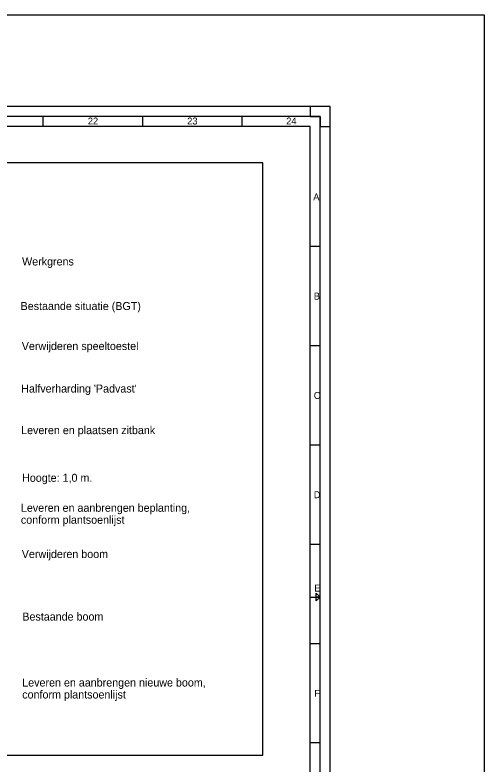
# Model space of a CAD drawing. Extents: x 192664 to 192925, y 446334 to 446521.
# Drawn here: x 192877.8 to 192925, y 446445.5 to 446521 of the extents above; entities that cross this region are included whole.
import ezdxf

# ---------------------------------------------------------------- set-up
doc = ezdxf.new("R2010")
doc.units = 0
for name, color, linetype in [('201011 legenda', 7, 'Continuous'), ('201020 hulplijnen', 7, 'Continuous'), ('X-XX-AL-TEKENBLAD-S', 7, 'Continuous'), ('X-XX-AL-TEKENBLAD_KADER-G', 7, 'Continuous')]:
    doc.layers.add(name, color=color, linetype=linetype)

msp = doc.modelspace()

# ---------------------------------------------------------------- linework, layer by layer
at = {"layer": '201020 hulplijnen'}
msp.add_lwpolyline([(192864.958, 446446.417), (192902.755, 446446.417), (192902.755, 446506.094), (192864.958, 446506.094)], close=True, dxfattribs=at)
at = {"layer": 'X-XX-AL-TEKENBLAD-S'}
for p, q in [((192909.543, 446511.756), (192671.743, 446511.756)), ((192909.543, 446343.556), (192909.543, 446511.756)), ((192908.543, 446510.756), (192674.743, 446510.756)), ((192880.643, 446510.756), (192880.643, 446509.756)), ((192890.643, 446510.756), (192890.643, 446509.756)), ((192900.643, 446510.756), (192900.643, 446509.756)), ((192908.543, 446344.556), (192908.543, 446510.756)), ((192908.543, 446497.656), (192907.543, 446497.656)), ((192908.543, 446487.656), (192907.543, 446487.656)), ((192908.543, 446477.656), (192907.543, 446477.656)), ((192908.543, 446467.656), (192907.543, 446467.656)), ((192907.543, 446462.356), (192908.543, 446462.356)), ((192908.143, 446462.356), (192908.543, 446462.356)), ((192908.543, 446462.356), (192908.143, 446462.356)), ((192908.543, 446457.656), (192907.543, 446457.656)), ((192908.543, 446447.656), (192907.543, 446447.656))]:
    msp.add_line(p, q, dxfattribs=at)
for points in [[(192909.543, 446509.756), (192909.543, 446511.756), (192907.543, 446511.756), (192907.543, 446510.756), (192908.543, 446510.756), (192908.543, 446509.756), (192909.543, 446509.756)], [(192908.143, 446462.356), (192908.143, 446462.756), (192908.543, 446462.356)], [(192908.543, 446462.356), (192908.143, 446461.956), (192908.143, 446462.356)]]:
    msp.add_lwpolyline(points, dxfattribs=at)
msp.add_lwpolyline([(192675.743, 446345.556), (192907.543, 446345.556), (192907.543, 446509.756), (192675.743, 446509.756)], close=True, dxfattribs=at)
at = {"layer": 'X-XX-AL-TEKENBLAD_KADER-G'}
msp.add_lwpolyline([(192664.22, 446520.974), (192925.029, 446520.974), (192925.029, 446333.894), (192664.22, 446333.894)], close=True, dxfattribs=at)

# ---------------------------------------------------------------- texts
at = {"layer": '201011 legenda'}
for s, p in [('Werkgrens', (192878.54, 446495.745)), ('Bestaande situatie (BGT)', (192878.389, 446491.259)), ('Verwijderen speeltoestel', (192878.508, 446487.23)), ("Halfverharding 'Padvast'", (192878.453, 446482.949)), ('Leveren en plaatsen zitbank', (192878.444, 446478.761)), ('Hoogte: 1,0 m. ', (192878.54, 446473.961)), ('Leveren en aanbrengen beplanting, ', (192878.421, 446470.941)), ('conform plantsoenlijst', (192878.421, 446469.734)), ('Verwijderen boom', (192878.508, 446466.285)), ('Bestaande boom', (192878.565, 446459.984)), ('Leveren en aanbrengen nieuwe boom, ', (192878.556, 446453.342)), ('conform plantsoenlijst', (192878.556, 446452.135))]:
    msp.add_text(s, height=0.8064, dxfattribs=at).set_placement(p)
at = {"layer": 'X-XX-AL-TEKENBLAD-S'}
for s, p in [('22', (192885.154, 446509.945)), ('23', (192895.153, 446509.945)), ('24', (192905.119, 446509.945)), ('A', (192907.843, 446502.306)), ('B', (192907.893, 446492.306)), ('C', (192907.893, 446482.306)), ('D', (192907.893, 446472.306)), ('E', (192907.943, 446462.906)), ('F', (192907.943, 446452.306))]:
    msp.add_text(s, height=0.7, dxfattribs=at).set_placement(p)

doc.saveas('drawing.dxf')
